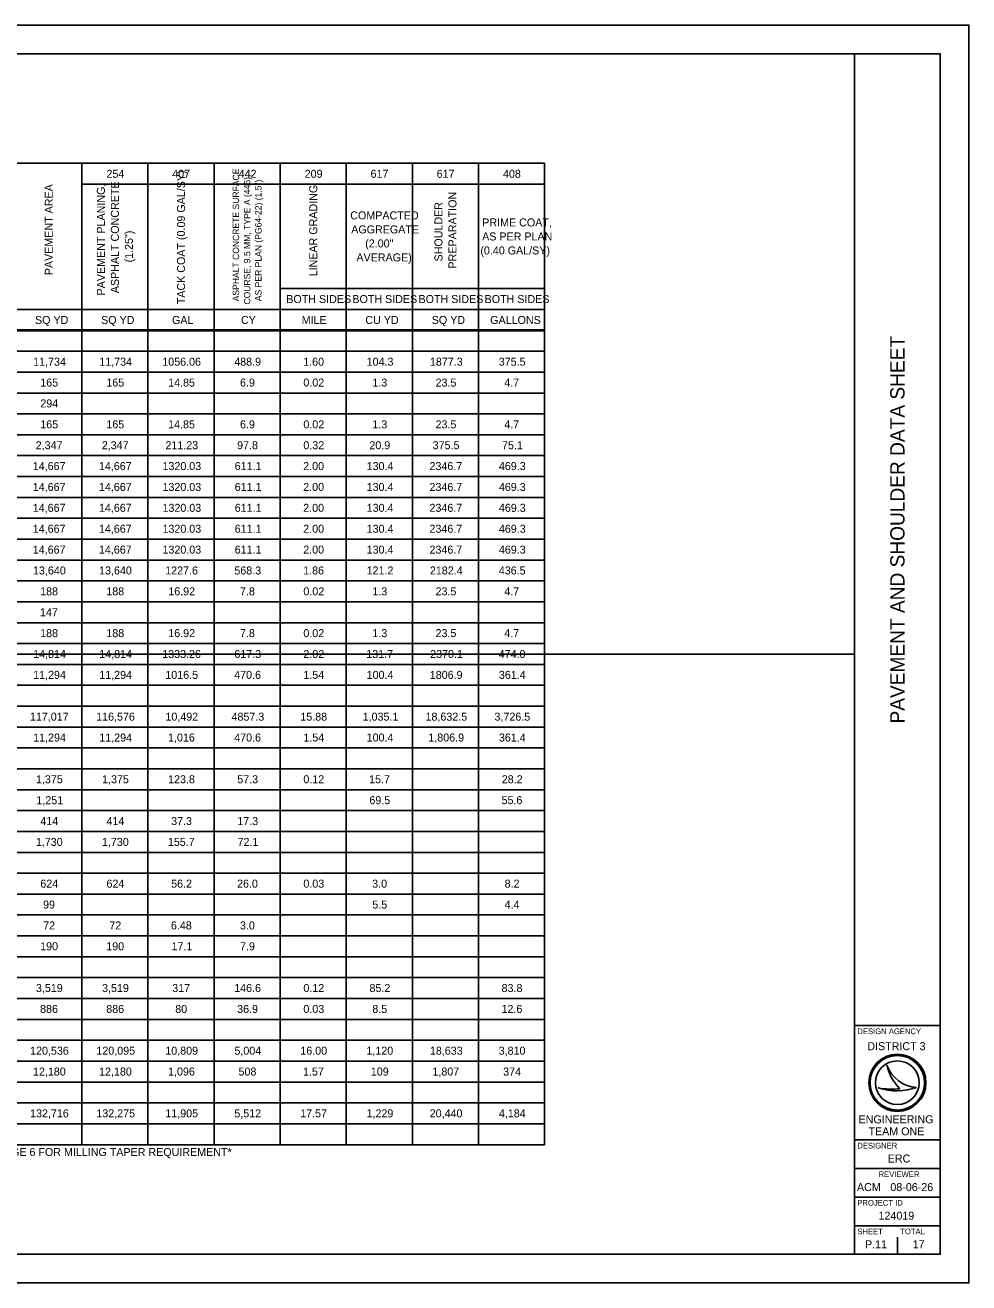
# Model space of a CAD drawing. Extents: x 0 to 34, y 0 to 22.
# Drawn here: x 17.49 to 34, y 0 to 22 of the extents above; entities that cross this region are included whole.
import ezdxf

# ---------------------------------------------------------------- set-up
doc = ezdxf.new("R2010")
doc.units = 0
for name, color, linetype in [('SC_Scratch1', 7, 'Continuous'), ('SH_Border', 7, 'Continuous'), ('SH_Cut_Line', 7, 'Continuous'), ('SH_Data', 7, 'Continuous')]:
    doc.layers.add(name, color=color, linetype=linetype)

msp = doc.modelspace()

# ---------------------------------------------------------------- linework, layer by layer
at = {"layer": 'SC_Scratch1'}
for p, q in [((1.5, 21.5), (32, 21.5)), ((1.5, 11), (32, 11))]:
    msp.add_line(p, q, dxfattribs=at)
at = {"layer": 'SH_Border'}
for p, q in [((32, 0.5), (32, 21.5)), ((32, 4.5), (33.5, 4.5)), ((32, 2.5), (33.5, 2.5)), ((32, 2), (33.5, 2)), ((32, 1.5), (33.5, 1.5)), ((32, 1), (33.5, 1))]:
    msp.add_line(p, q, dxfattribs=at)
msp.add_lwpolyline([(1.5, 21.5), (33.5, 21.5), (33.5, 0.5), (1.5, 0.5)], close=True, dxfattribs=at)
at = {"layer": 'SH_Cut_Line'}
msp.add_lwpolyline([(0, 0), (34, 0), (34, 22), (0, 22)], close=True, dxfattribs=at)
at = {"layer": 'SH_Data'}
for p, q in [((6.92, 19.583), (26.58, 19.583)), ((18.485, 19.583), (18.485, 16.671)), ((19.641, 19.583), (19.641, 16.671)), ((20.798, 19.583), (20.798, 16.671)), ((21.954, 19.583), (21.954, 16.671)), ((23.111, 19.583), (23.111, 16.671)), ((24.267, 19.583), (24.267, 16.671)), ((25.424, 19.583), (25.424, 16.671)), ((26.58, 19.583), (26.58, 16.651)), ((18.485, 19.217), (26.58, 19.217)), ((21.954, 17.391), (26.58, 17.391)), ((17.328, 17.026), (26.58, 17.026)), ((6.92, 16.671), (26.58, 16.671)), ((6.92, 16.651), (26.58, 16.651)), ((18.485, 16.651), (18.485, 2.417)), ((19.641, 16.651), (19.641, 2.417)), ((20.798, 16.651), (20.798, 2.417)), ((21.954, 16.651), (21.954, 2.417)), ((23.111, 16.651), (23.111, 2.417)), ((24.267, 16.651), (24.267, 2.417)), ((25.424, 16.651), (25.424, 2.417)), ((26.58, 16.671), (26.58, 2.417)), ((6.92, 16.296), (26.58, 16.296)), ((6.92, 15.93), (26.58, 15.93)), ((6.92, 15.565), (26.58, 15.565)), ((6.92, 15.2), (26.58, 15.2)), ((6.92, 14.835), (26.58, 14.835)), ((6.92, 14.47), (26.58, 14.47)), ((6.92, 14.104), (26.58, 14.104)), ((6.92, 13.739), (26.58, 13.739)), ((6.92, 13.374), (26.58, 13.374)), ((6.92, 13.009), (26.58, 13.009)), ((6.92, 12.643), (26.58, 12.643)), ((6.92, 12.278), (26.58, 12.278)), ((6.92, 11.913), (26.58, 11.913)), ((6.92, 11.548), (26.58, 11.548)), ((6.92, 11.183), (26.58, 11.183)), ((6.92, 10.817), (26.58, 10.817)), ((6.92, 10.452), (26.58, 10.452)), ((6.92, 10.087), (26.58, 10.087)), ((6.92, 9.722), (26.58, 9.722)), ((6.92, 9.357), (26.58, 9.357)), ((6.92, 8.991), (26.58, 8.991)), ((6.92, 8.626), (26.58, 8.626)), ((6.92, 8.261), (26.58, 8.261)), ((6.92, 7.896), (26.58, 7.896)), ((6.92, 7.53), (26.58, 7.53)), ((6.92, 7.165), (26.58, 7.165)), ((6.92, 6.8), (26.58, 6.8)), ((6.92, 6.435), (26.58, 6.435)), ((6.92, 6.07), (26.58, 6.07)), ((6.92, 5.704), (26.58, 5.704)), ((6.92, 5.339), (26.58, 5.339)), ((6.92, 4.974), (26.58, 4.974)), ((6.92, 4.609), (26.58, 4.609)), ((6.92, 4.243), (26.58, 4.243)), ((6.92, 3.878), (26.58, 3.878)), ((32.567, 3.81), (32.567, 3.81)), ((6.92, 3.513), (26.58, 3.513)), ((32.417, 3.41), (32.417, 3.41)), ((32.75, 3.5), (32.75, 3.5)), ((33.087, 3.419), (33.087, 3.419)), ((6.92, 3.148), (26.58, 3.148)), ((6.92, 2.783), (26.58, 2.783)), ((6.92, 2.417), (26.58, 2.417)), ((32.375, 0.675), (32.375, 0.675)), ((32.75, 0.5), (32.75, 0.8))]:
    msp.add_line(p, q, dxfattribs=at)
for radius in [0.5, 0.477, 0.477, 0.382]:
    msp.add_circle((32.75, 3.5), radius, dxfattribs=at)
for centre, radius, start, end in [((33.116, 3.998), 0.58, 198.9257, 198.9319), ((33.347, 3.97), 0.796, 191.6379, 191.6421), ((33.116, 3.998), 0.58, 198.9319, 267.1657), ((33.347, 3.97), 0.796, 191.6421, 226.0947), ((32.739, 4.37), 1.013, 251.4576, 290.0832), ((32.648, 4.654), 1.266, 259.4964, 259.4995), ((32.739, 4.37), 1.013, 251.4527, 251.4576), ((32.648, 4.654), 1.266, 259.4995, 276.6672)]:
    msp.add_arc(centre, radius, start, end, dxfattribs=at)

# ---------------------------------------------------------------- texts
for s, height, p in [('254', 0.14, (18.916, 19.33)), ('407', 0.14, (20.066, 19.33)), ('442', 0.14, (21.228, 19.33)), ('209', 0.14, (22.383, 19.33)), ('617', 0.14, (23.535, 19.33)), ('617', 0.14, (24.692, 19.33)), ('408', 0.14, (25.852, 19.33)), ('COMPACTED ', 0.14, (23.18, 18.602)), ('AGGREGATE ', 0.14, (23.197, 18.357)), ('PRIME COAT, ', 0.14, (25.489, 18.479)), ('AS PER PLAN ', 0.14, (25.487, 18.234)), ('(2.00" ', 0.14, (23.442, 18.112)), ('(0.40 GAL/SY)', 0.14, (25.456, 17.989)), ('AVERAGE)', 0.14, (23.288, 17.867)), ('BOTH SIDES', 0.14, (22.061, 17.139)), ('BOTH SIDES', 0.14, (23.217, 17.139)), ('BOTH SIDES', 0.14, (24.374, 17.139)), ('BOTH SIDES', 0.14, (25.53, 17.139)), ('SQ YD', 0.14, (17.666, 16.773)), ('SQ YD', 0.14, (18.822, 16.773)), ('GAL', 0.14, (20.062, 16.773)), ('CY', 0.14, (21.269, 16.773)), ('MILE', 0.14, (22.331, 16.773)), ('CU YD', 0.14, (23.444, 16.773)), ('SQ YD', 0.14, (24.605, 16.773)), ('GALLONS', 0.14, (25.628, 16.773)), ('11,734', 0.14, (17.634, 16.043)), ('11,734', 0.14, (18.79, 16.043)), ('1056.06', 0.14, (19.892, 16.043)), ('488.9', 0.14, (21.151, 16.043)), ('1.60', 0.14, (22.357, 16.043)), ('104.3', 0.14, (23.467, 16.043)), ('1877.3', 0.14, (24.573, 16.043)), ('375.5', 0.14, (25.778, 16.043)), ('165', 0.14, (17.758, 15.678)), ('165', 0.14, (18.914, 15.678)), ('14.85', 0.14, (19.995, 15.678)), ('6.9', 0.14, (21.252, 15.678)), ('0.02', 0.14, (22.36, 15.678)), ('1.3', 0.14, (23.567, 15.678)), ('23.5', 0.14, (24.672, 15.678)), ('4.7', 0.14, (25.874, 15.678)), ('294', 0.14, (17.759, 15.313)), ('165', 0.14, (17.758, 14.947)), ('165', 0.14, (18.914, 14.947)), ('14.85', 0.14, (19.995, 14.947)), ('6.9', 0.14, (21.252, 14.947)), ('0.02', 0.14, (22.36, 14.947)), ('1.3', 0.14, (23.567, 14.947)), ('23.5', 0.14, (24.672, 14.947)), ('4.7', 0.14, (25.874, 14.947)), ('2,347', 0.14, (17.678, 14.582)), ('2,347', 0.14, (18.834, 14.582)), ('211.23', 0.14, (19.947, 14.582)), ('97.8', 0.14, (21.201, 14.582)), ('0.32', 0.14, (22.36, 14.582)), ('20.9', 0.14, (23.515, 14.582)), ('375.5', 0.14, (24.622, 14.582)), ('75.1', 0.14, (25.835, 14.582)), ('14,667', 0.14, (17.627, 14.217)), ('14,667', 0.14, (18.784, 14.217)), ('1320.03', 0.14, (19.896, 14.217)), ('611.1', 0.14, (21.159, 14.217)), ('2.00', 0.14, (22.357, 14.217)), ('130.4', 0.14, (23.467, 14.217)), ('2346.7', 0.14, (24.566, 14.217)), ('469.3', 0.14, (25.78, 14.217)), ('14,667', 0.14, (17.627, 13.852)), ('14,667', 0.14, (18.784, 13.852)), ('1320.03', 0.14, (19.896, 13.852)), ('611.1', 0.14, (21.159, 13.852)), ('2.00', 0.14, (22.357, 13.852)), ('130.4', 0.14, (23.467, 13.852)), ('2346.7', 0.14, (24.566, 13.852)), ('469.3', 0.14, (25.78, 13.852)), ('14,667', 0.14, (17.627, 13.487)), ('14,667', 0.14, (18.784, 13.487)), ('1320.03', 0.14, (19.896, 13.487)), ('611.1', 0.14, (21.159, 13.487)), ('2.00', 0.14, (22.357, 13.487)), ('130.4', 0.14, (23.467, 13.487)), ('2346.7', 0.14, (24.566, 13.487)), ('469.3', 0.14, (25.78, 13.487)), ('14,667', 0.14, (17.627, 13.121)), ('14,667', 0.14, (18.784, 13.121)), ('1320.03', 0.14, (19.896, 13.121)), ('611.1', 0.14, (21.159, 13.121)), ('2.00', 0.14, (22.357, 13.121)), ('130.4', 0.14, (23.467, 13.121)), ('2346.7', 0.14, (24.566, 13.121)), ('469.3', 0.14, (25.78, 13.121)), ('14,667', 0.14, (17.627, 12.756)), ('14,667', 0.14, (18.784, 12.756)), ('1320.03', 0.14, (19.896, 12.756)), ('611.1', 0.14, (21.159, 12.756)), ('2.00', 0.14, (22.357, 12.756)), ('130.4', 0.14, (23.467, 12.756)), ('2346.7', 0.14, (24.566, 12.756)), ('469.3', 0.14, (25.78, 12.756)), ('13,640', 0.14, (17.631, 12.391)), ('13,640', 0.14, (18.787, 12.391)), ('1227.6', 0.14, (19.943, 12.391)), ('568.3', 0.14, (21.153, 12.391)), ('1.86', 0.14, (22.356, 12.391)), ('121.2', 0.14, (23.466, 12.391)), ('2182.4', 0.14, (24.573, 12.391)), ('436.5', 0.14, (25.778, 12.391)), ('188', 0.14, (17.756, 12.026)), ('188', 0.14, (18.913, 12.026)), ('16.92', 0.14, (19.997, 12.026)), ('7.8', 0.14, (21.251, 12.026)), ('0.02', 0.14, (22.36, 12.026)), ('1.3', 0.14, (23.567, 12.026)), ('23.5', 0.14, (24.672, 12.026)), ('4.7', 0.14, (25.874, 12.026)), ('147', 0.14, (17.753, 11.66)), ('188', 0.14, (17.756, 11.295)), ('188', 0.14, (18.913, 11.295)), ('16.92', 0.14, (19.997, 11.295)), ('7.8', 0.14, (21.251, 11.295)), ('0.02', 0.14, (22.36, 11.295)), ('1.3', 0.14, (23.567, 11.295)), ('23.5', 0.14, (24.672, 11.295)), ('4.7', 0.14, (25.874, 11.295)), ('14,814', 0.14, (17.634, 10.93)), ('14,814', 0.14, (18.79, 10.93)), ('1333.26', 0.14, (19.892, 10.93)), ('617.3', 0.14, (21.153, 10.93)), ('2.02', 0.14, (22.36, 10.93)), ('131.7', 0.14, (23.46, 10.93)), ('2370.1', 0.14, (24.578, 10.93)), ('474.0', 0.14, (25.776, 10.93)), ('11,294', 0.14, (17.634, 10.565)), ('11,294', 0.14, (18.79, 10.565)), ('1016.5', 0.14, (19.945, 10.565)), ('470.6', 0.14, (21.15, 10.565)), ('1.54', 0.14, (22.36, 10.565)), ('100.4', 0.14, (23.467, 10.565)), ('1806.9', 0.14, (24.571, 10.565)), ('361.4', 0.14, (25.78, 10.565)), ('117,017', 0.14, (17.577, 9.834)), ('116,576', 0.14, (18.736, 9.834)), ('10,492', 0.14, (19.947, 9.834)), ('4857.3', 0.14, (21.103, 9.834)), ('15.88', 0.14, (22.307, 9.834)), ('1,035.1', 0.14, (23.397, 9.834)), ('18,632.5', 0.14, (24.496, 9.834)), ('3,726.5', 0.14, (25.703, 9.834)), ('11,294', 0.14, (17.634, 9.469)), ('11,294', 0.14, (18.79, 9.469)), ('1,016', 0.14, (19.993, 9.469)), ('470.6', 0.14, (21.15, 9.469)), ('1.54', 0.14, (22.36, 9.469)), ('100.4', 0.14, (23.467, 9.469)), ('1,806.9', 0.14, (24.546, 9.469)), ('361.4', 0.14, (25.78, 9.469)), ('1,375', 0.14, (17.683, 8.739)), ('1,375', 0.14, (18.839, 8.739)), ('123.8', 0.14, (19.994, 8.739)), ('57.3', 0.14, (21.204, 8.739)), ('0.12', 0.14, (22.36, 8.739)), ('15.7', 0.14, (23.51, 8.739)), ('28.2', 0.14, (25.83, 8.739)), ('1,251', 0.14, (17.69, 8.373)), ('69.5', 0.14, (23.515, 8.373)), ('55.6', 0.14, (25.826, 8.373)), ('414', 0.14, (17.759, 8.008)), ('414', 0.14, (18.916, 8.008)), ('37.3', 0.14, (20.047, 8.008)), ('17.3', 0.14, (21.204, 8.008)), ('1,730', 0.14, (17.681, 7.643)), ('1,730', 0.14, (18.837, 7.643)), ('155.7', 0.14, (19.99, 7.643)), ('72.1', 0.14, (21.209, 7.643)), ('624', 0.14, (17.759, 6.913)), ('624', 0.14, (18.916, 6.913)), ('56.2', 0.14, (20.047, 6.913)), ('26.0', 0.14, (21.2, 6.913)), ('0.03', 0.14, (22.36, 6.913)), ('3.0', 0.14, (23.564, 6.913)), ('8.2', 0.14, (25.88, 6.913)), ('99', 0.14, (17.807, 6.547)), ('5.5', 0.14, (23.566, 6.547)), ('4.4', 0.14, (25.88, 6.547)), ('72', 0.14, (17.809, 6.182)), ('72', 0.14, (18.966, 6.182)), ('6.48', 0.14, (20.044, 6.182)), ('3.0', 0.14, (21.251, 6.182)), ('190', 0.14, (17.756, 5.817)), ('190', 0.14, (18.912, 5.817)), ('17.1', 0.14, (20.053, 5.817)), ('7.9', 0.14, (21.252, 5.817)), ('3,519', 0.14, (17.682, 5.087)), ('3,519', 0.14, (18.839, 5.087)), ('317', 0.14, (20.066, 5.087)), ('146.6', 0.14, (21.15, 5.087)), ('0.12', 0.14, (22.36, 5.087)), ('85.2', 0.14, (23.516, 5.087)), ('83.8', 0.14, (25.827, 5.087)), ('886', 0.14, (17.755, 4.721)), ('886', 0.14, (18.912, 4.721)), ('80', 0.14, (20.119, 4.721)), ('36.9', 0.14, (21.202, 4.721)), ('0.03', 0.14, (22.36, 4.721)), ('8.5', 0.14, (23.566, 4.721)), ('12.6', 0.14, (25.826, 4.721)), ('DESIGN AGENCY', 0.1, (32.05, 4.35)), ('DISTRICT 3', 0.14, (32.224, 4.07)), ('120,536', 0.14, (17.58, 3.991)), ('120,095', 0.14, (18.739, 3.991)), ('10,809', 0.14, (19.945, 3.991)), ('5,004', 0.14, (21.154, 3.991)), ('16.00', 0.14, (22.307, 3.991)), ('1,120', 0.14, (23.463, 3.991)), ('18,633', 0.14, (24.573, 3.991)), ('3,810', 0.14, (25.776, 3.991)), ('12,180', 0.14, (17.631, 3.626)), ('12,180', 0.14, (18.787, 3.626)), ('1,096', 0.14, (19.993, 3.626)), ('508', 0.14, (21.226, 3.626)), ('1.57', 0.14, (22.354, 3.626)), ('109', 0.14, (23.54, 3.626)), ('1,807', 0.14, (24.617, 3.626)), ('374', 0.14, (25.855, 3.626)), ('132,716', 0.14, (17.58, 2.895)), ('132,275', 0.14, (18.739, 2.895)), ('11,905', 0.14, (19.946, 2.895)), ('5,512', 0.14, (21.153, 2.895)), ('17.57', 0.14, (22.304, 2.895)), ('1,229', 0.14, (23.465, 2.895)), ('20,440', 0.14, (24.57, 2.895)), ('4,184', 0.14, (25.78, 2.895)), ('ENGINEERING', 0.14, (32.071, 2.79)), ('TEAM ONE', 0.14, (32.244, 2.58)), ('DESIGNER', 0.1, (32.05, 2.35)), ('* = STILL USE TYPICAL 1 BUT SEE NOTE FOR ITEM 254 - PAVEMENT PLANING ASPHALT CONCRETE (1.25") ON PAGE 6 FOR MILLING TAPER REQUIREMENT*', 0.14, (6.98, 2.218)), ('ERC', 0.14, (32.581, 2.105)), ('REVIEWER', 0.1, (32.422, 1.85)), ('ACM', 0.14, (32.043, 1.605)), ('08-06-26', 0.14, (32.627, 1.605)), ('PROJECT ID', 0.1, (32.05, 1.35)), ('124019', 0.14, (32.42, 1.105)), ('SHEET', 0.1, (32.05, 0.85)), ('TOTAL', 0.1, (32.8, 0.85)), ('P.11', 0.14, (32.184, 0.605)), ('17', 0.14, (33.018, 0.605))]:
    msp.add_text(s, height=height, dxfattribs=at).set_placement(p)
for s, height, p in [('TACK COAT (0.09 GAL/SY)', 0.14, (20.29, 17.118)), ('ASPHALT CONCRETE SURFACE ', 0.112, (21.236, 17.169)), ('COURSE, 9.5 MM, TYPE A (446), ', 0.112, (21.432, 17.112)), ('PAVEMENT AREA', 0.14, (17.977, 17.626)), ('PAVEMENT PLANING, ', 0.14, (18.888, 17.272)), ('ASPHALT CONCRETE ', 0.14, (19.133, 17.311)), ('AS PER PLAN (PG64-22) (1.5")', 0.112, (21.628, 17.172)), ('LINEAR GRADING', 0.14, (22.603, 17.606)), ('PREPARATION', 0.14, (25.038, 17.743)), ('SHOULDER ', 0.14, (24.793, 17.866)), ('(1.25")', 0.14, (19.378, 17.85)), ('PAVEMENT AND SHOULDER DATA SHEET', 0.25, (32.875, 9.784))]:
    msp.add_text(s, height=height, rotation=90, dxfattribs=at).set_placement(p)

doc.saveas('drawing.dxf')
